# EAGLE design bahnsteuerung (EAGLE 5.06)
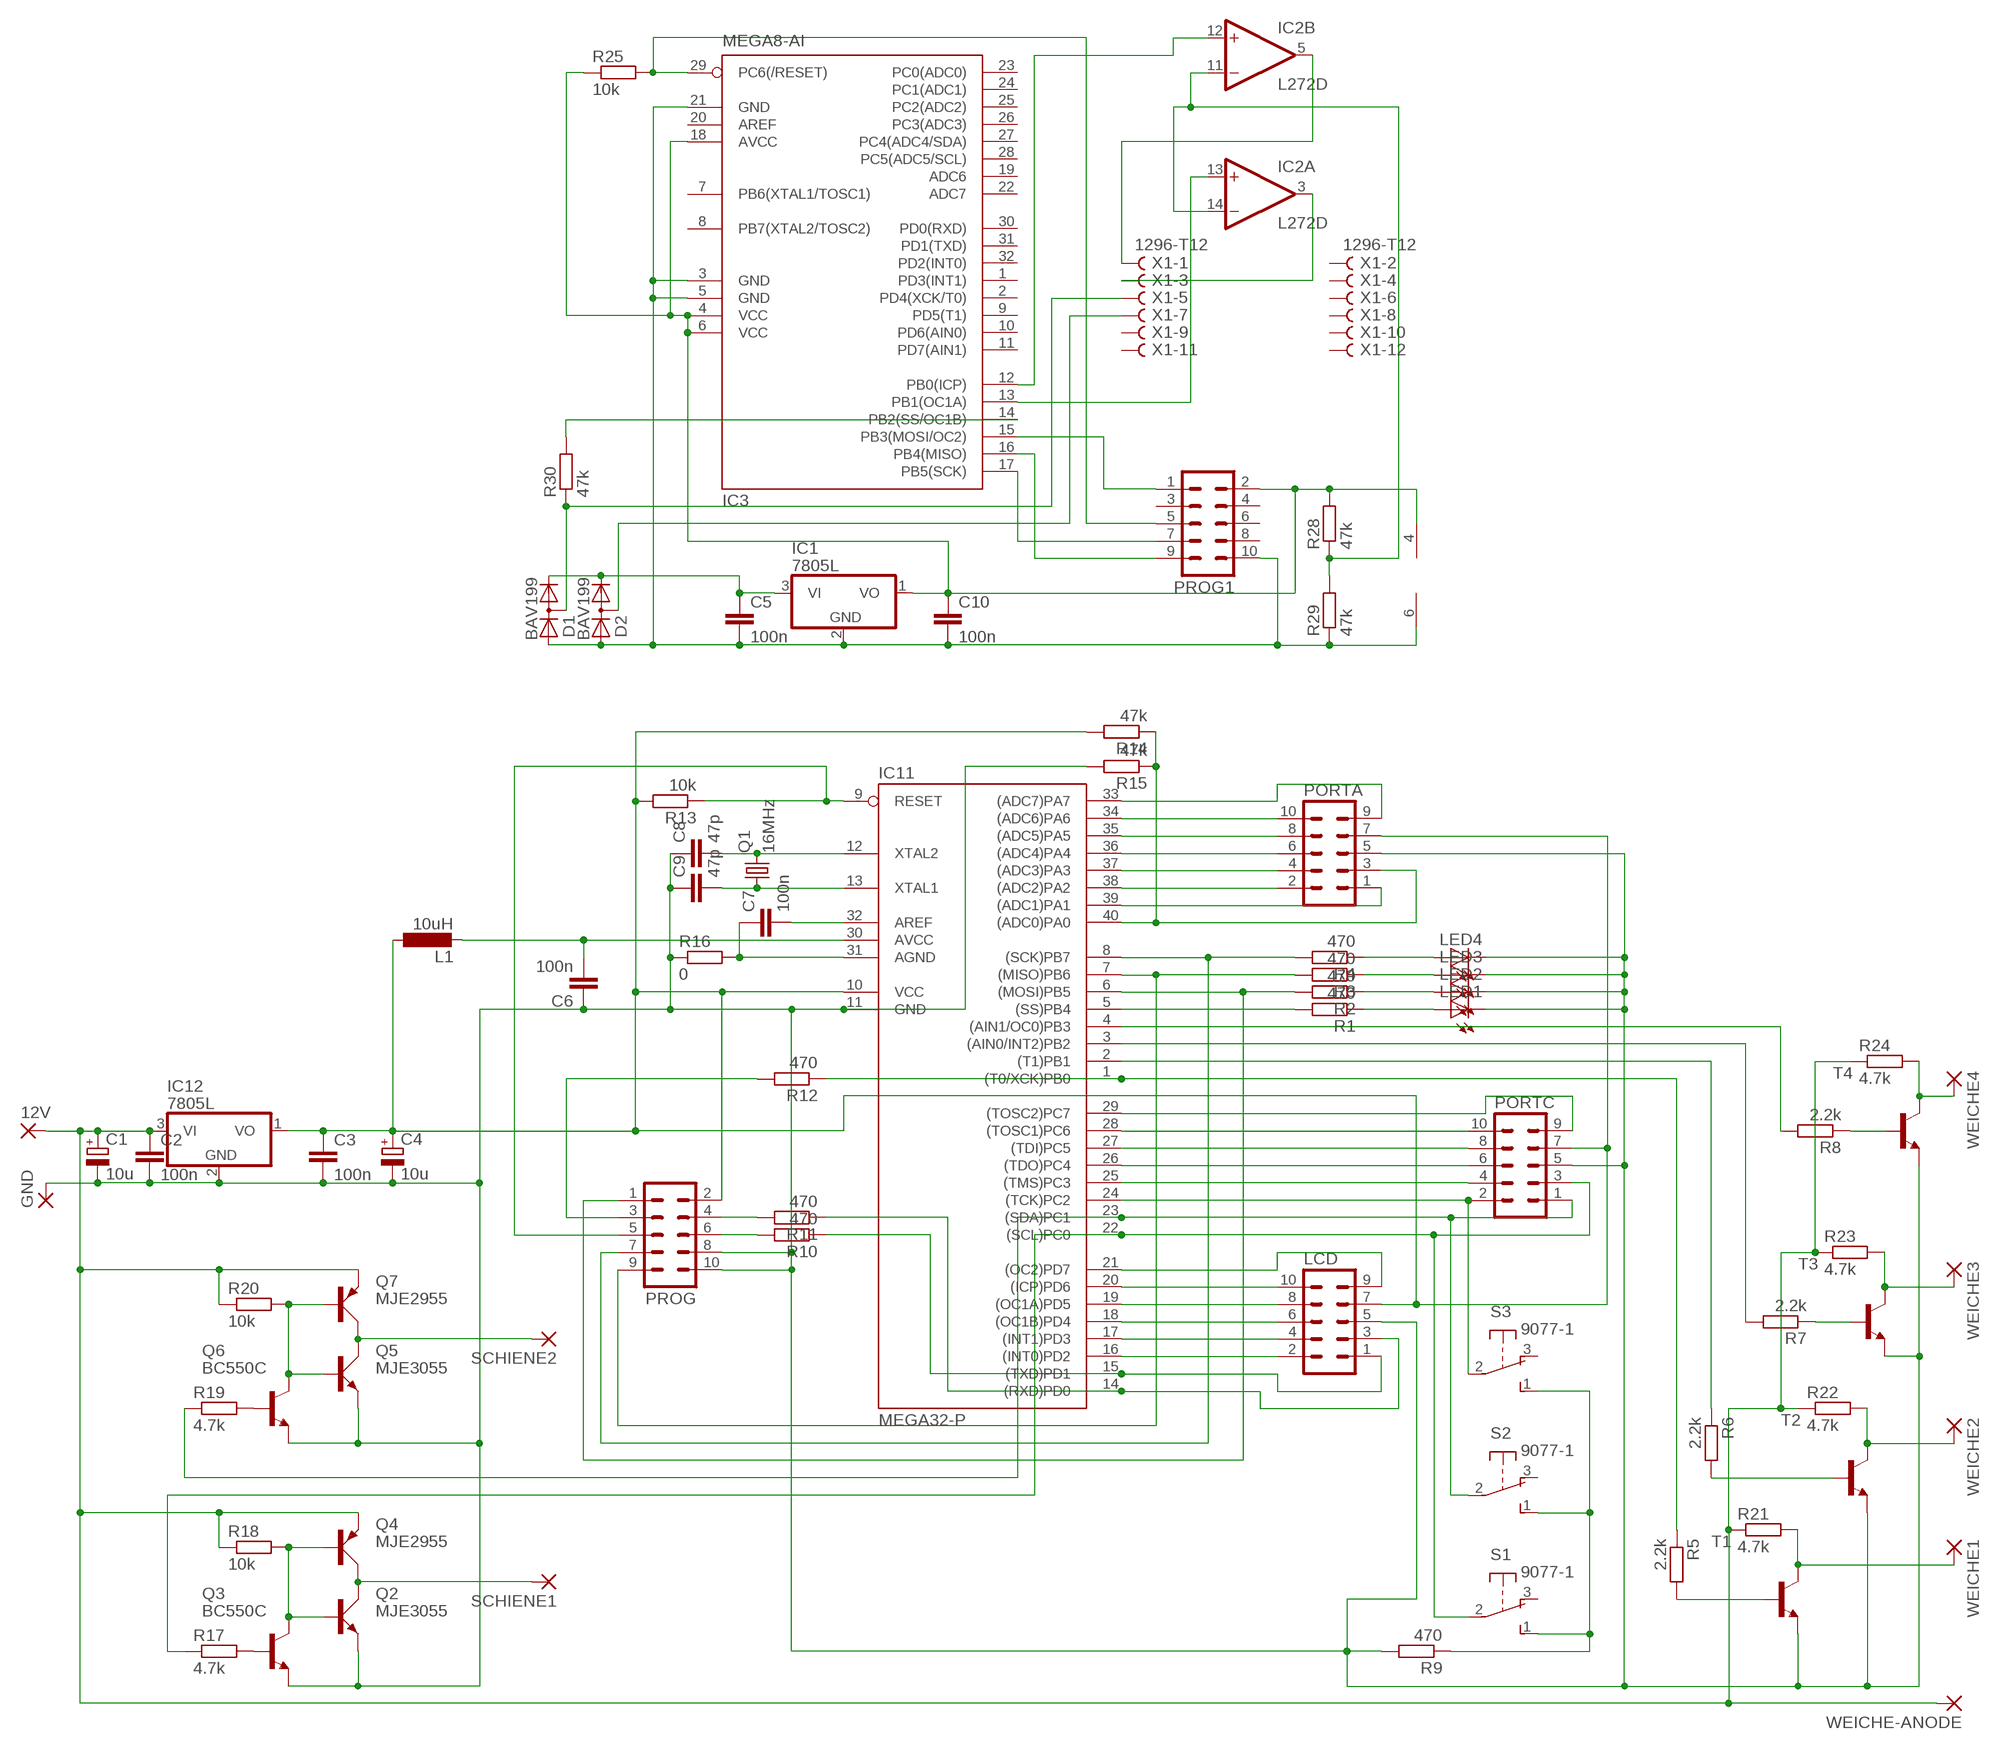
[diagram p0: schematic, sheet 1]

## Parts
12V  1,6/0,8  [1,6/0,8]
C1  10u  CPOL-EUE2.5-5  [E2,5-5]
C2  100n  C5/2.5  [C5B2.5]
C3  100n  C5/2.5  [C5B2.5]
C4  10u  CPOL-EUE2.5-5  [E2,5-5]
C5  100n  C-EUC0402  [C0402]
C6  100n  C5/2.5  [C5B2.5]
C7  100n  C2.5/2  [C2.5-2]
C8  47p  C2.5/2  [C2.5-2]
C9  47p  C2.5/2  [C2.5-2]
C10  100n  C-EUC0402  [C0402]
D1  BAV199  [SOT23]
D2  BAV199  [SOT23]
GND  1,6/0,8  [1,6/0,8]
IC1  7805L  [TO92]
IC2  L272D  [SO16]
IC3  MEGA8-AI  [TQFP32-08]
IC11  MEGA32-P  [DIL40]
IC12  7805L  [TO92]
L1  10uH  L-EU0204/7  [0204/7@1]
LCD  ML10  [ML10]
LED1  LED3MM  [LED3MM]
LED2  LED3MM  [LED3MM]
LED3  LED3MM  [LED3MM]
LED4  LED3MM  [LED3MM]
PORTA  ML10  [ML10]
PORTC  ML10  [ML10]
PROG  ML10  [ML10]
PROG1  ML10  [ML10]
Q1  16MHz  CRYTALHC49U-V  [HC49U-V]
Q2  MJE3055  [TO220AV]
Q3  BC550C  [TO92-EBC]
Q4  MJE2955  [TO220AV@1]
Q5  MJE3055  [TO220AV]
Q6  BC550C  [TO92-EBC]
Q7  MJE2955  [TO220AV@1]
R1  470  R-EU_0204/7  [0204/7]
R2  470  R-EU_0204/7  [0204/7]
R3  470  R-EU_0204/7  [0204/7]
R4  470  R-EU_0204/7  [0204/7]
R5  2.2k  R-EU_0204/7  [0204/7]
R6  2.2k  R-EU_0204/7  [0204/7]
R7  2.2k  R-EU_0204/7  [0204/7]
R8  2.2k  R-EU_0204/7  [0204/7]
R9  470  R-EU_0204/7  [0204/7]
R10  470  R-EU_0204/7  [0204/7]
R11  470  R-EU_0204/7  [0204/7]
R12  470  R-EU_0204/7  [0204/7]
R13  10k  R-EU_0204/7  [0204/7]
R14  47k  R-EU_0204/7  [0204/7]
R15  47k  R-EU_0204/7  [0204/7]
R16  0  R-EU_0204/2V  [0204V]
R17  4.7k  R-EU_0204/2V  [0204V]
R18  10k  R-EU_0204/7  [0204/7]
R19  4.7k  R-EU_0204/2V  [0204V]
R20  10k  R-EU_0204/7  [0204/7]
R21  4.7k  R-EU_0204/2V  [0204V]
R22  4.7k  R-EU_0204/2V  [0204V]
R23  4.7k  R-EU_0204/2V  [0204V]
R24  4.7k  R-EU_0204/2V  [0204V]
R25  10k  R-EU_MELF0102R  [MINI_MELF-0102R]
R28  47k  R-EU_MELF0102R  [MINI_MELF-0102R]
R29  47k  R-EU_MELF0102R  [MINI_MELF-0102R]
R30  47k  R-EU_MELF0102R  [MINI_MELF-0102R]
S1  9077-1  [9077-1]
S2  9077-1  [9077-1]
S3  9077-1  [9077-1]
SCHIENE1  1,6/0,8  [1,6/0,8]
SCHIENE2  1,6/0,8  [1,6/0,8]
T1  -NPN-TO220V  [TO220V]
T2  -NPN-TO220V  [TO220V]
T3  -NPN-TO220V  [TO220V]
T4  -NPN-TO220V  [TO220V]
WEICHE1  1,6/0,8  [1,6/0,8]
WEICHE2  1,6/0,8  [1,6/0,8]
WEICHE3  1,6/0,8  [1,6/0,8]
WEICHE4  1,6/0,8  [1,6/0,8]
WEICHE-ANODE  1,6/0,8  [1,6/0,8]
X1  1296-T12  [1296-12]

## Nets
AGND [mitteldick]: C7.1 IC11.31(AGND) R16.2
AREF [mitteldick]: C7.2 IC11.32(AREF)
AVCC [mitteldick]: C6.2 IC11.30(AVCC) L1.2
GND [mitteldick]: C1.- C2.2 C3.2 C4.- C6.1 C8.1 C9.1 GND.1(P) IC11.11(GND) IC12.2(GND) LCD.5 LED1.K(C) LED2.K(C) LED3.K(C) LED4.K(C) PORTA.5 PORTC.5 PROG.8 PROG.10 Q2.E Q3.E Q5.E Q6.E R9.2 R15.2 R16.1 T1.3(E) T2.3(E) T3.3(E) T4.3(E)
GND1: C5.2 C10.2 D1.1(A) D2.1(A) IC1.2(GND) IC2.6(P:GND) IC3.3(GND) IC3.5(GND) IC3.21(GND) PROG1.10 R29.1
N$1: IC11.22((SCL)PC0) PORTC.3 R17.1 S1.2(P)
N$2: IC11.23((SDA)PC1) PORTC.1 R19.1 S2.2(P)
N$3: R8.1 T4.1(B)
N$4: IC11.4((AIN1/OC0)PB3) R8.2
N$5: R24.2 T4.2(C) WEICHE4.1(P)
N$6: IC11.5((SS)PB4) R1.2
N$7: LED1.A R1.1
N$8: LED2.A R2.1
N$9: LED3.A R3.1
N$10: LED4.A R4.1
N$11 [mitteldick]: IC11.16((INT0)PD2) LCD.2
N$12 [mitteldick]: IC11.17((INT1)PD3) LCD.4
N$13 [mitteldick]: IC11.18((OC1B)PD4) LCD.6
N$14 [mitteldick]: IC11.19((OC1A)PD5) LCD.8
N$15 [mitteldick]: IC11.20((ICP)PD6) LCD.10
N$16 [mitteldick]: IC11.21((OC2)PD7) LCD.9
N$17 [mitteldick]: IC11.25((TMS)PC3) PORTC.4
N$18 [mitteldick]: IC11.26((TDO)PC4) PORTC.6
N$19 [mitteldick]: IC11.27((TDI)PC5) PORTC.8
N$20 [mitteldick]: IC11.28((TOSC1)PC6) PORTC.10
N$21 [mitteldick]: IC11.29((TOSC2)PC7) PORTC.9
N$22 [mitteldick]: IC11.39((ADC1)PA1) PORTA.1
N$23 [mitteldick]: IC11.38((ADC2)PA2) PORTA.2
N$24 [mitteldick]: IC11.37((ADC3)PA3) PORTA.4
N$25 [mitteldick]: IC11.36((ADC4)PA4) PORTA.6
N$26 [mitteldick]: IC11.35((ADC5)PA5) PORTA.8
N$27 [mitteldick]: IC11.34((ADC6)PA6) PORTA.10
N$28 [mitteldick]: IC11.33((ADC7)PA7) PORTA.9
N$29 [mitteldick]: R9.1 S1.1(S) S2.1(S) S3.1(S)
N$30: Q6.B R19.2
N$31: Q3.B R17.2
N$32: Q2.C Q4.C SCHIENE1.1(P)
N$34: Q2.B Q3.C Q4.B R18.2
N$35: Q5.C Q7.C SCHIENE2.1(P)
N$37: Q5.B Q6.C Q7.B R20.2
N$38: IC2.3(A:OUT) X1.3
N$40: IC3.29(PC6(/RESET)) PROG1.5 R25.2
N$41: IC3.16(PB4(MISO)) PROG1.9
N$42: IC3.17(PB5(SCK)) PROG1.7
N$43: IC3.15(PB3(MOSI/OC2)) PROG1.1
N$44: D1.3(AC) R30.1 X1.5
N$45: C5.1 D1.2(C) D2.2(C) IC1.3(VI)
N$46: D2.3(AC) X1.7
N$52: IC2.5(B:OUT) X1.1
N$53: IC2.13(A:+IN) IC3.13(PB1(OC1A))
N$54: IC2.12(B:+IN) IC3.12(PB0(ICP))
N$55: IC2.11(B:-IN) IC2.14(A:-IN) R28.1 R29.2
N$56: IC3.14(PB2(SS/OC1B)) R30.2
N$122: IC11.40((ADC0)PA0) PORTA.3 R14.1 R15.1
N$135: IC11.6((MOSI)PB5) PROG.1 R2.2
N$136: IC11.7((MISO)PB6) PROG.9 R3.2
N$147: IC11.14((RXD)PD0) LCD.3 R11.1
N$149: R7.1 T3.1(B)
N$150: IC11.1((T0/XCK)PB0) R5.1 R12.1
N$152: C8.2 IC11.12(XTAL2) Q1.2
N$153: C9.2 IC11.13(XTAL1) Q1.1
N$156: IC11.9(RESET) PROG.5 R13.1
N$157: PROG.4 R11.2
N$158: PROG.6 R10.2
N$159: PROG.3 R12.2
N$160: IC11.24((TCK)PC2) PORTC.2 S3.2(P)
N$161: IC11.15((TXD)PD1) LCD.1 R10.1
N$164: IC11.3((AIN0/INT2)PB2) R7.2
N$166: IC11.2((T1)PB1) R6.1
N$167: R5.2 T1.1(B)
N$168: R6.2 T2.1(B)
N$170: IC11.8((SCK)PB7) PROG.7 R4.2
N$172 [mitteldick]: R21.2 T1.2(C) WEICHE1.1(P)
N$173 [mitteldick]: R22.2 T2.2(C) WEICHE2.1(P)
N$174 [mitteldick]: R23.2 T3.2(C) WEICHE3.1(P)
VCC [mitteldick]: C3.1 C4.+ IC11.10(VCC) IC12.1(VO) L1.1 LCD.7 PORTA.7 PORTC.7 PROG.2 R13.2 R14.2
VCC1 [mitteldick]: 12V.1(P) C1.+ C2.1 IC12.3(VI) Q4.E Q7.E R18.1 R20.1 R21.1 R22.1 R23.1 R24.1 WEICHE-ANODE.1(P)
VCC2: C10.1 IC1.1(VO) IC2.4(P:V+) IC3.4(VCC) IC3.6(VCC) IC3.18(AVCC) PROG1.2 R25.1 R28.2
Unconnected: IC3.1(PD3(INT1)) IC3.2(PD4(XCK/T0)) IC3.7(PB6(XTAL1/TOSC1)) IC3.8(PB7(XTAL2/TOSC2)) IC3.9(PD5(T1)) IC3.10(PD6(AIN0)) IC3.11(PD7(AIN1)) IC3.19(ADC6) IC3.20(AREF) IC3.22(ADC7) IC3.23(PC0(ADC0)) IC3.24(PC1(ADC1)) IC3.25(PC2(ADC2)) IC3.26(PC3(ADC3)) IC3.27(PC4(ADC4/SDA)) IC3.28(PC5(ADC5/SCL)) IC3.30(PD0(RXD)) IC3.31(PD1(TXD)) IC3.32(PD2(INT0)) PROG1.3 PROG1.4 PROG1.6 PROG1.8 S1.3(O) S2.3(O) S3.3(O) X1.2 X1.4 X1.6 X1.8 X1.9 X1.10 X1.11 X1.12

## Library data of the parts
12V GND SCHIENE1 SCHIENE2 WEICHE1-WEICHE4 WEICHE-ANODE = wirepad:1,6/0,8: THROUGH-HOLE PAD
C1 C4 = rcl:CPOL-EU: POLARIZED CAPACITOR, European symbol
C2 C3 C6-C9 = capacitor-wima:C: CAPACITOR
C5 C10 = rcl:C-EU: CAPACITOR, European symbol
D1 D2 = diode:BAV199: DIODE low-leakage double diode
IC1 IC12 = linear:78*: Positive VOLTAGE REGULATOR Source: http://cache.national.com/ds/LM/LM78L05.pdf http://www.fairchildsemi.com/ds/LM/LM7805.pdf
IC2 = linear:L272: OP AMP
IC3 = atmel:MEGA8: MICROCONTROLLER 8 Kbytes FLASH, 1 kbytes SRAM, 512 bytes EEPROM, USART, 6-channel 10 bit ADC, 2-channel 8 bit ADC Pin compatible with Atmega48, ATMega88, ATMega168 Source: avr.lbr
IC11 = atmel:MEGA32-P: MICROCONTROLLER 32 Kbytes FLASH 2 Kbytes SRAM 1 Kbytes EEPROM USART 8-channel 10 bit ADC Source: www.atmel.com .. doc2503.pdf
L1 = rcl:L-EU: INDUCTOR, European symbol
LCD PORTA PORTC PROG PROG1 = con-harting-ml:ML10: HARTING
LED1-LED4 = led:LED: LED
Q1 = crystal:CRYTAL: CRYSTAL
Q2 Q5 = transistor-power:MJE3055: NPN TRANSISTOR
Q3 Q6 = transistor-npn:BC550*: NPN Transistor
Q4 Q7 = transistor-power:MJE2955: PNP TRANSISTOR
R1-R25 R28-R30 = rcl:R-EU_: RESISTOR, European symbol
S1-S3 = switch-misc:9077-1: MARQUARDT SWITCH
T1-T4 = transistor:*-NPN-: NPN Transistror
X1 = con-leotronics:1296-T12: 1.27mm SINGLE ROW FEMALE SOCKET Source: http://www.leotronics.co.uk/Conexcon/Data%20Sheets/sec.%20A/1296ing.pdf

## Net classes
1 dick: width 1.016 mm, clearance 0.61 mm
2 mitteldick: width 0.762 mm

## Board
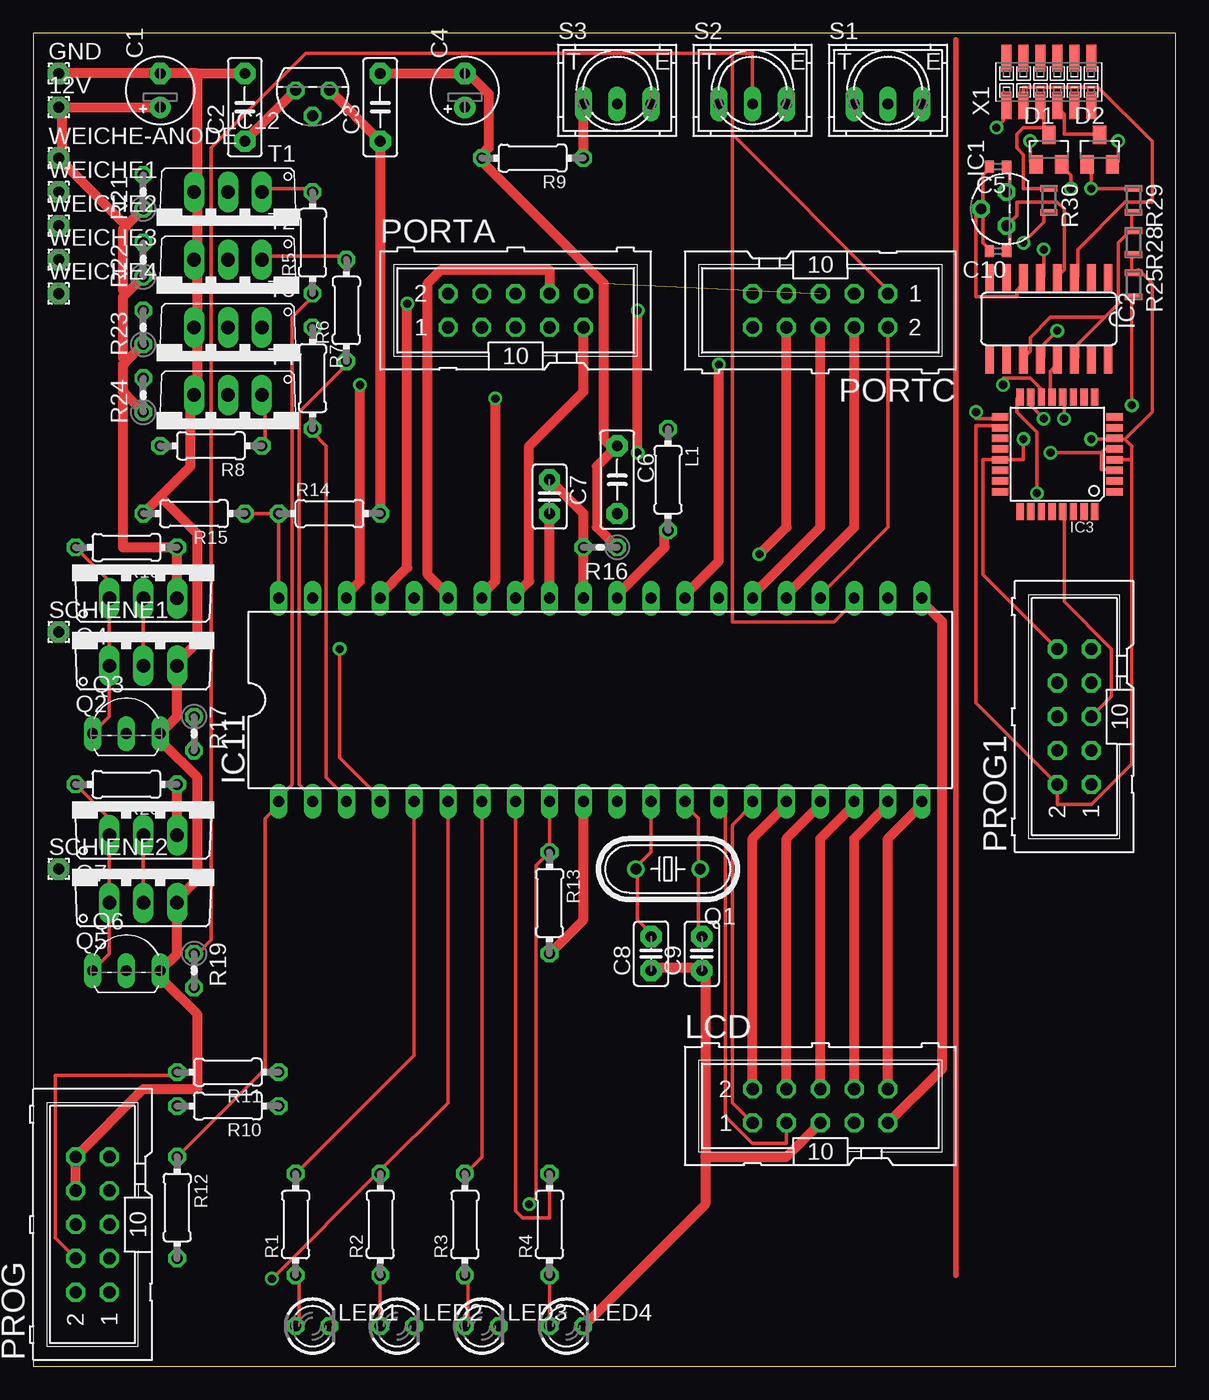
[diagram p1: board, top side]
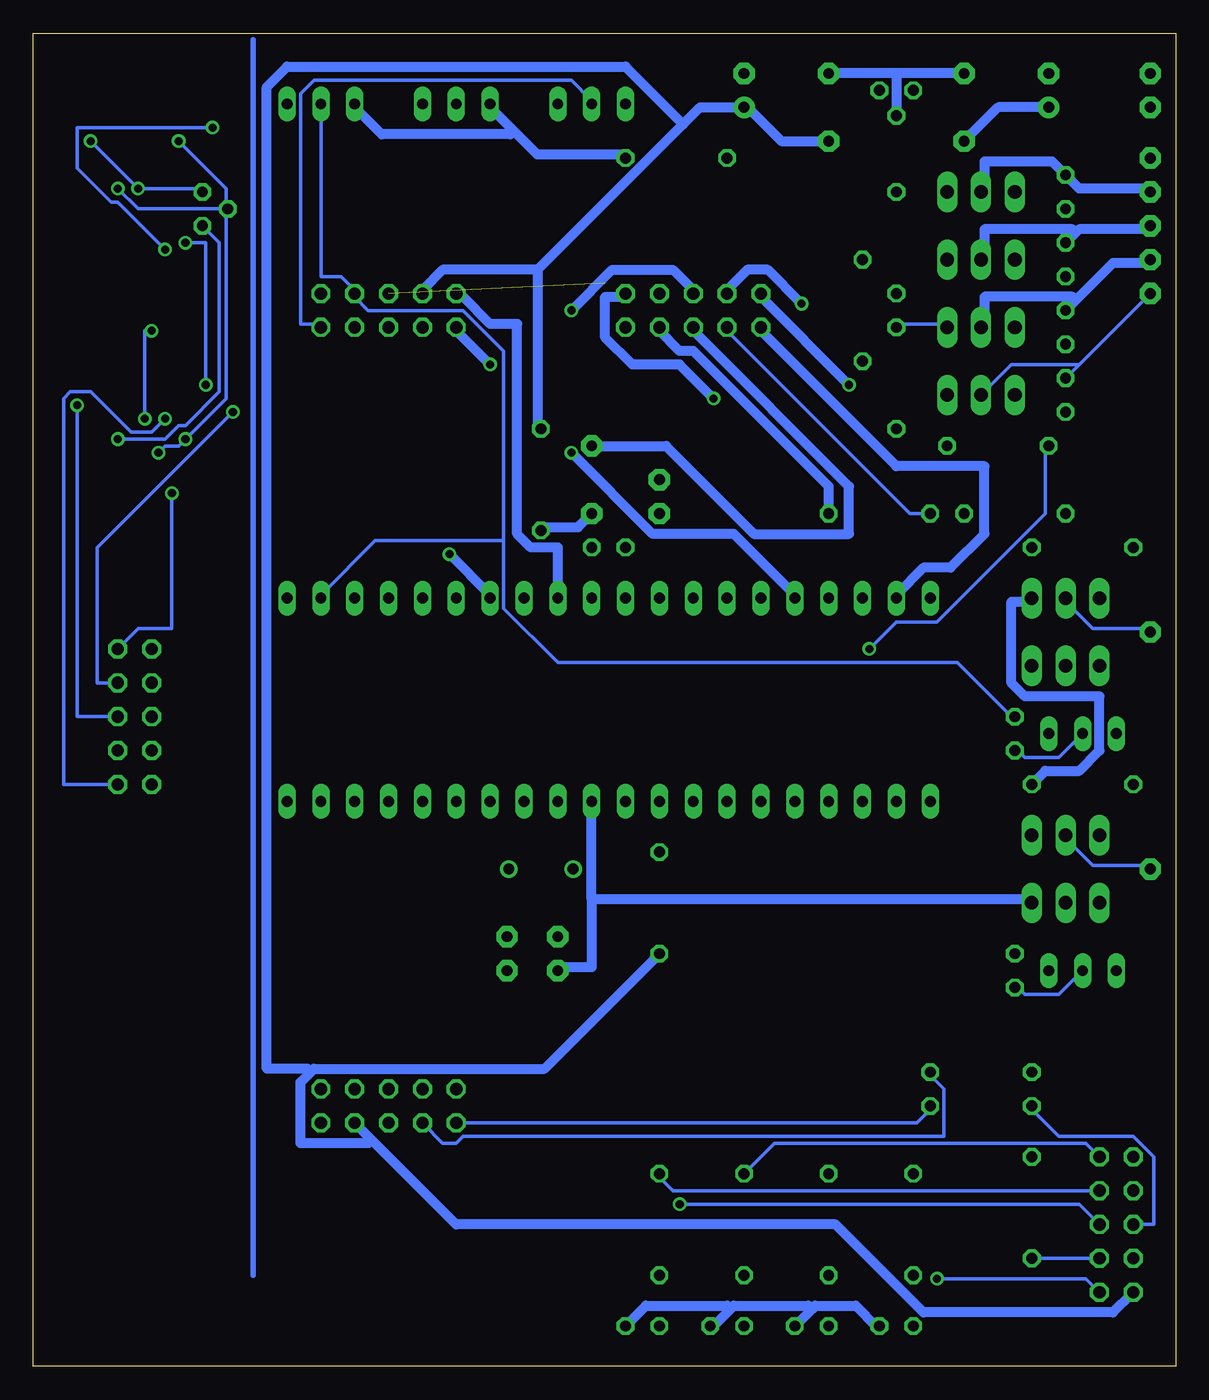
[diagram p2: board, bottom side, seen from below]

Size 85.7 x 100 mm. Coordinates in mm from the lower left corner, seen from the top.
Outline: 0,0 85.7,0 85.7,100 0,100 0,0
Copper layers (1*16): Top 0.035mm / dielectric 1.5mm / Bottom 0.035mm
Design rules "default": minimum track width 10mil, minimum drill 24mil, track to track 8mil, track to pad 8mil, pad to pad 8mil, via to via 8mil, smd to smd 8mil, copper to edge 40mil, drill to drill 8mil, minimum pad ring 10mil, minimum via ring 8mil, stop-mask expansion 4mil, vias tented up to drill 0mil, thermal gap 10mil

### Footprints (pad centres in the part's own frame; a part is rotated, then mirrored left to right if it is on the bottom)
1,6/0,8 = drill 0.813 pad 1.6 octagon: 1 0,0
E2,5-5 = drill 0.813 pad 1.6 round: + -1.27,0 | drill 0.813 pad 1.6 octagon: - 1.27,0
C5B2.5 = drill 0.813 pad 1.6 octagon: 1 -2.54,0; 2 2.54,0
C0402 = smd 0.7 x 0.9: 1 -0.65,0; 2 0.65,0
C2.5-2 = drill 0.813 pad 1.6 octagon: 1 -1.27,0; 2 1.27,0
SOT23 = smd 1 x 1.4: 1 -0.95,-1.1; 2 0.95,-1.1; 3 0,1.1
TO92 = drill 0.813 octagon: 1 -1.27,0; 2 0,1.905; 3 1.27,0
SO16 = smd 0.66 x 2.032: 1 -4.445,-3.073; 2 -3.175,-3.073; 3 -1.905,-3.073; 4 -0.635,-3.073; 5 0.635,-3.073; 6 1.905,-3.073; 7 3.175,-3.073; 8 4.445,-3.073; 9 4.445,3.073; 10 3.175,3.073; 11 1.905,3.073; 12 0.635,3.073; 13 -0.635,3.073; 14 -1.905,3.073; 15 -3.175,3.073; 16 -4.445,3.073
TQFP32-08 = smd 1.27 x 0.559: 1 -4.293,2.8; 2 -4.293,2; 3 -4.293,1.2; 4 -4.293,0.4; 5 -4.293,-0.4; 6 -4.293,-1.2; 7 -4.293,-2; 8 -4.293,-2.8; 17 4.293,-2.8; 18 4.293,-2; 19 4.293,-1.2; 20 4.293,-0.4; 21 4.293,0.4; 22 4.293,1.2; 23 4.293,2; 24 4.293,2.8 | smd 0.559 x 1.27: 9 -2.8,-4.293; 10 -2,-4.293; 11 -1.2,-4.293; 12 -0.4,-4.293; 13 0.4,-4.293; 14 1.2,-4.293; 15 2,-4.293; 16 2.8,-4.293; 25 2.8,4.293; 26 2,4.293; 27 1.2,4.293; 28 0.4,4.293; 29 -0.4,4.293; 30 -1.2,4.293; 31 -2,4.293; 32 -2.8,4.293
DIL40 = drill 0.813 long: 1 -24.13,-7.62; 2 -21.59,-7.62; 3 -19.05,-7.62; 4 -16.51,-7.62; 5 -13.97,-7.62; 6 -11.43,-7.62; 7 -8.89,-7.62; 8 -6.35,-7.62; 9 -3.81,-7.62; 10 -1.27,-7.62; 11 1.27,-7.62; 12 3.81,-7.62; 13 6.35,-7.62; 14 8.89,-7.62; 15 11.43,-7.62; 16 13.97,-7.62; 17 16.51,-7.62; 18 19.05,-7.62; 19 21.59,-7.62; 20 24.13,-7.62; 21 24.13,7.62; 22 21.59,7.62; 23 19.05,7.62; 24 16.51,7.62; 25 13.97,7.62; 26 11.43,7.62; 27 8.89,7.62; 28 6.35,7.62; 29 3.81,7.62; 30 1.27,7.62; 31 -1.27,7.62; 32 -3.81,7.62; 33 -6.35,7.62; 34 -8.89,7.62; 35 -11.43,7.62; 36 -13.97,7.62; 37 -16.51,7.62; 38 -19.05,7.62; 39 -21.59,7.62; 40 -24.13,7.62
0204/7@1 = drill 0.813 octagon: 1 -3.81,0; 2 3.81,0
ML10 = drill 0.914 octagon: 1 -5.08,-1.27; 2 -5.08,1.27; 3 -2.54,-1.27; 4 -2.54,1.27; 5 0,-1.27; 6 0,1.27; 7 2.54,-1.27; 8 2.54,1.27; 9 5.08,-1.27; 10 5.08,1.27
LED3MM = drill 0.813 octagon: A -1.27,0; K 1.27,0
HC49U-V = drill 0.813 round: 1 -2.413,0; 2 2.413,0
TO220AV = drill 1.016 long: B -2.54,-2.54; C 0,-2.54; E 2.54,-2.54
TO92-EBC = drill 0.813 long: B 0,-1.27; C -2.54,-1.27; E 2.54,-1.27
TO220AV@1 = drill 1.016 long: B -2.54,-2.54; C 0,-2.54; E 2.54,-2.54
0204/7 = drill 0.813 octagon: 1 -3.81,0; 2 3.81,0
0204V = drill 0.813 octagon: 1 -1.27,0; 2 1.27,0
MINI_MELF-0102R = smd 0.5 x 1.3: 1 -0.9,0; 2 0.9,0
9077-1 = drill 0.813 long: 1 -2.54,-1.016; 2 0,-1.016; 3 2.54,-1.016
TO220V = drill 1.016 long: 1 -2.54,-2.54; 2 0,-2.54; 3 2.54,-2.54
1296-12 = smd 0.76 x 2.05: 1 -3.175,-1.78; 2 -3.175,1.78; 3 -1.905,-1.78; 4 -1.905,1.78; 5 -0.635,-1.78; 6 -0.635,1.78; 7 0.635,-1.78; 8 0.635,1.78; 9 1.905,-1.78; 10 1.905,1.78; 11 3.175,-1.78; 12 3.175,1.78

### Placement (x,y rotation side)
12V  1.9,94.45 0 top
C1  9.52,95.72 90 top
C2  15.87,94.45 90 top
C3  26.03,94.45 90 top
C4  32.38,95.72 90 top
C5  72.38,90 180 top
C6  43.81,66.51 270 top
C7  38.73,65.24 270 top
C8  46.35,30.95 90 top
C9  50.16,30.95 90 top
C10  72.38,83.66 180 top
D1  76.19,91.28 0 top
D2  80,91.28 0 top
GND  1.9,96.99 0 top
IC1  73.02,86.83 90 top
IC2  76.19,78.58 180 top
IC3  76.83,68.41 180 top
IC11  42.54,50 0 top
IC12  20.95,95.72 180 top
L1  47.62,66.51 270 top
LCD  59.05,19.52 0 top
LED1  20.95,3.01 0 top
LED2  27.3,3.01 0 top
LED3  33.65,3.01 0 top
LED4  40,3.01 0 top
PORTA  36.19,79.21 0 top
PORTC  59.05,79.21 180 top
PROG  4.44,10.63 90 top
PROG1  78.1,48.73 90 top
Q1  47.62,37.3 180 top
Q2  8.25,55.08 0 top
Q3  6.98,48.73 0 top
Q4  8.25,60.16 0 top
Q5  8.25,37.3 0 top
Q6  6.98,30.95 0 top
Q7  8.25,42.38 0 top
R1  19.68,10.63 90 top
R2  26.03,10.63 90 top
R3  32.38,10.63 90 top
R4  38.73,10.63 90 top
R5  20.95,84.29 90 top
R6  23.49,79.21 90 top
R7  20.95,74.13 270 top
R8  13.33,69.05 180 top
R9  37.46,90.64 180 top
R10  14.6,19.52 180 top
R11  14.6,22.06 180 top
R12  10.79,11.9 270 top
R13  38.73,34.76 270 top
R14  22.22,63.97 0 top
R15  12.06,63.97 180 top
R16  42.54,61.43 180 top
R17  12.06,47.46 270 top
R18  6.98,61.43 180 top
R19  12.06,29.68 270 top
R20  6.98,43.65 180 top
R21  8.25,88.1 90 top
R22  8.25,83.02 90 top
R23  8.25,77.94 90 top
R24  8.25,72.86 90 top
R25  82.55,81.11 270 top
R28  82.55,84.29 270 top
R29  82.55,87.47 270 top
R30  76.19,87.47 270 top
S1  64.13,95.72 0 top
S2  53.97,95.72 0 top
S3  43.81,95.72 0 top
SCHIENE1  1.9,55.08 0 top
SCHIENE2  1.9,37.3 0 top
T1  14.6,85.56 180 top
T2  14.6,80.48 180 top
T3  14.6,75.4 180 top
T4  14.6,70.32 180 top
WEICHE1  1.9,88.1 0 top
WEICHE2  1.9,85.56 0 top
WEICHE3  1.9,83.02 0 top
WEICHE4  1.9,80.48 0 top
WEICHE-ANODE  1.9,90.64 0 top
X1  76.19,96.36 0 top

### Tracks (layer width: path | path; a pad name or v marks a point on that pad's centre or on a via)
AGND
  Top 0.762: IC11.31 R16.2 41.27,63.97 C7.1
AREF
  Top 0.762: IC11.32 C7.2
AVCC
  Top 0.762: IC11.30 43.81,57.87 47.37,61.43 47.37,62.45 L1.2
  Bottom 0.762: C6.2 44.83,62.95 47.37,62.95 L1.2
GND  (1 unrouted)
  Top 0.762: R16.1 42.29,62.95 42.29,67.53 C6.1 43.3,69.05 42.79,69.56 42.79,81.24 33.65,90.39 R9.2 33.65,90.89 34.16,91.4 34.16,95.47 32.63,96.99 C4.- C3.2 | GND.1 C1.- 12.31,96.99 | 12.31,96.99 C2.2 | LCD.5 56.51,15.71 50.41,15.71 | 50.41,15.71 50.41,29.43 C9.1 49.91,29.93 46.35,29.93 C8.1 | LED4.K 50.41,12.15 50.41,15.71 | PROG.8 PROG.10 8.25,20.79 12.31,20.79 12.31,26.38 9.77,28.92 9.77,29.43 Q6.E 10.79,30.95 Q5.E 10.79,35.01 12.31,36.54 12.31,44.16 9.77,46.7 9.77,47.21 Q3.E 10.79,48.73 Q2.E 10.79,52.79 12.31,54.32 12.31,62.45 9.52,65.24 | 9.52,65.24 11.81,67.53 11.81,72.61 T4.3 12.31,73.11 12.31,77.69 T3.3 12.31,78.19 12.31,82.77 T2.3 12.31,83.27 12.31,87.85 T1.3 12.31,88.35 12.31,96.99 | 9.52,65.24 R15.2
  Bottom 0.762: C6.1 38.22,69.05 31.62,62.45 24.51,62.45 24.51,66 36.19,77.69 PORTA.5 | C2.2 20.95,96.99 | 20.95,96.99 IC12.2 | 20.95,96.99 C3.2 | 27.3,4.28 LED2.K | 27.3,4.28 27.05,4.53 24,4.53 22.47,3.01 LED1.K | 33.4,4.28 33.14,4.53 27.55,4.53 27.3,4.28 | 33.4,4.28 34.67,3.01 LED3.K | LED4.K 39.75,4.53 33.65,4.53 33.4,4.28 | 43.81,35.01 43.81,29.93 46.35,29.93 C8.1 | 43.81,35.01 IC11.11 | 43.81,35.01 10.79,35.01 Q5.E
GND1  (via drill 0.61)
  Top 0.254: PROG1.10 71.24,59.4 71.24,68.03 72.26,68.03 IC3.21 72.77,68.03 74.29,68.03 v74.29,69.56 | R29.1 82.42,88.35 v79.37,88.35 79.37,89.88 D2.1 | 71.24,86.83 71.24,84.29 71.75,83.78 C10.2 | 71.24,86.83 71.24,89.37 71.75,89.88 C5.2 | 71.24,86.83 IC1.2 70.73,86.83 70.73,80.23 73.78,80.23 73.78,80.73 74.29,81.24 IC2.6 | v74.8,91.91 74.8,90.39 D1.1 | 80.13,68.54 80.13,67.27 80.89,67.27 IC3.3 | 80.13,68.54 80.39,68.8 80.89,68.8 IC3.5 | v76.32,68.54 80.13,68.54
  Bottom 0.254: v74.8,91.91 71.24,88.35 71.24,86.83 | v79.37,88.35 77.85,86.83 71.24,86.83 | 71.24,86.83 71.24,72.61 v74.29,69.56 74.8,69.05 75.81,69.05 v76.32,68.54 | 71.24,86.83 IC1.2
N$1
  Bottom 0.254: S1.2 64.13,81.75 62.61,81.75 61.59,80.73 PORTC.3 61.59,80.23 60.57,79.21 53.46,79.21 50.41,76.16 50.41,61.94 | 50.41,61.94 50.41,56.86 46.35,52.79 16.38,52.79 12.31,48.73 R17.1 | 50.41,61.94 60.07,61.94 64.13,57.87 IC11.22
N$2
  Top 0.254: 52.45,98.51 53.97,98.51 S2.2 | 52.45,98.51 20.44,98.51 13.33,91.4 13.33,31.97 12.31,30.95 R19.1 | 52.45,98.51 52.45,92.42 | 52.45,92.42 52.45,55.84 60.07,55.84 61.59,57.37 IC11.23 | 52.45,92.42 64.13,80.73 PORTC.1
N$3
  Top 0.254: R8.1 17.39,69.05 17.39,72.61 T4.1
N$4  (via drill 0.61)
  Top 0.254: v22.98,53.81 22.98,45.68 26.03,42.63 IC11.4
  Bottom 0.254: v22.98,53.81 20.95,55.84 17.9,55.84 9.77,63.97 9.77,69.05 R8.2
N$5
  Bottom 0.254: 7.23,75.15 R24.2 | WEICHE4.1 7.23,75.15 | 7.23,75.15 12.31,75.15 T4.2
N$6
  Top 0.254: R1.2 28.57,23.33 IC11.5
N$7
  Top 0.254: LED1.A 19.93,3.01 19.93,6.57 R1.1
N$8
  Top 0.254: LED2.A R2.1
N$9
  Top 0.254: LED3.A 32.63,3.01 32.63,6.57 R3.1
N$10
  Top 0.254: LED4.A R4.1
N$11
  Top 0.762: LCD.2 53.97,39.59 56.51,42.13 IC11.16
N$12
  Top 0.762: LCD.4 56.51,39.59 59.05,42.13 IC11.17
N$13
  Top 0.762: LCD.6 59.05,39.59 61.59,42.13 IC11.18
N$14
  Top 0.762: LCD.8 61.59,39.59 64.13,42.13 IC11.19
N$15
  Top 0.762: LCD.10 64.13,39.59 66.67,42.13 IC11.20
N$16
  Top 0.762: LCD.9 68.19,22.31 68.19,55.84 66.67,57.37 IC11.21
N$17
  Top 0.762: IC11.25 56.51,57.87 61.59,62.95 PORTC.4
N$18
  Top 0.762: IC11.26 53.97,57.87 59.05,62.95 PORTC.6
N$19  (via drill 0.61)
  Top 0.762: v54.48,60.92 56.51,62.95 PORTC.8
  Bottom 0.762: v54.48,60.92 51.43,57.87 IC11.27
N$20  (via drill 0.61)
  Top 0.762: v51.43,75.15 51.43,60.41 48.89,57.87 IC11.28
  Bottom 0.762: v51.43,75.15 53.97,77.69 PORTC.10
N$21
  Bottom 0.762: IC11.29 46.35,61.43 48.38,61.43 49.4,62.45 49.4,78.19 51.43,78.19 53.46,80.23 53.97,80.23 PORTC.9
N$22
  Bottom 0.762: IC11.39 20.95,57.87 18.92,59.91 16.89,59.91 14.35,62.45 14.35,67.53 20.95,67.53 31.11,77.69 PORTA.1
N$23  (via drill 0.61)
  Top 0.762: v24.51,73.62 24.51,58.89 23.49,57.87 IC11.38
  Bottom 0.762: v24.51,73.62 31.11,80.23 PORTA.2
N$24  (via drill 0.61)
  Top 0.762: v28.06,79.72 28.06,59.91 26.03,57.87 IC11.37
  Bottom 0.762: v28.06,79.72 30.6,82.26 32.13,82.26 33.65,80.73 PORTA.4
N$25  (via drill 0.61)
  Top 0.762: v45.33,68.54 v45.33,79.21
  Bottom 0.762: v45.33,68.54 39.24,62.45 33.14,62.45 28.57,57.87 IC11.36 | v45.33,79.21 42.29,82.26 37.71,82.26 36.19,80.73 PORTA.6
N$26
  Top 0.762: IC11.35 31.11,57.87 29.59,59.4 29.59,81.24 30.6,82.26 38.73,82.26 PORTA.8
N$27  (via drill 0.61)
  Top 0.762: v34.67,72.61 34.67,58.89 33.65,57.87 IC11.34
  Bottom 0.762: v34.67,72.61 37.21,75.15 40.76,75.15 42.79,77.18 42.79,80.23 41.27,80.23 PORTA.10
N$28
  Top 0.762: IC11.33 36.19,57.87 37.21,58.89 37.21,69.05 41.27,73.11 PORTA.9
N$29
  Top 0.762: R9.1 S3.1
  Bottom 0.762: 49.65,92.67 47.87,90.89 41.27,90.89 R9.1 | 49.65,92.67 51.43,94.45 S2.1 | S1.1 61.59,94.45 59.56,92.42 49.91,92.42 49.65,92.67
N$30
  Bottom 0.254: Q6.B 8.76,27.9 11.3,27.9 11.81,28.41 R19.2
N$31
  Bottom 0.254: Q3.B 8.76,45.68 11.3,45.68 11.81,46.19 R17.2
N$32
  Top 0.254: Q4.C Q2.C
  Bottom 0.254: SCHIENE1.1 2.15,55.33 6.22,55.33 8.25,57.37 Q4.C
N$33
  Bottom 0.406: 69.21,6.82 69.21,99.53
N$34
  Top 0.254: R18.2 5.71,58.89 Q4.B Q2.B 5.71,48.73 Q3.C
N$35
  Top 0.254: Q7.C Q5.C
  Bottom 0.254: SCHIENE2.1 2.15,37.55 6.22,37.55 8.25,39.59 Q7.C
N$36
  Top 0.406: 69.21,6.82 69.21,99.53
N$37
  Top 0.254: R20.2 5.71,41.11 Q7.B Q5.B 5.71,30.95 Q6.C
N$38
  Top 0.254: IC2.3 78.35,81.75 78.35,83.78 81.91,87.34 83.94,87.34 83.94,91.91 79.88,95.97 74.29,95.97 X1.3
N$40  (via drill 0.61)
  Top 0.254: PROG1.5 80.89,50.25 80.89,53.81 77.34,57.37 77.34,63.97 IC3.29 | v82.42,72.1 82.42,80.23 R25.2
  Bottom 0.254: v82.42,72.1 82.42,48.73 PROG1.5
N$41  (via drill 0.61)
  Top 0.254: v75.31,65.49 75.31,70.07 73.78,71.59 73.78,72.61 IC3.16
  Bottom 0.254: v75.31,65.49 75.31,55.33 77.85,55.33 PROG1.9
N$42  (via drill 0.61)
  Top 0.254: v70.73,71.59 70.73,71.08 72.26,71.08 IC3.17
  Bottom 0.254: v70.73,71.59 80.89,61.43 80.89,51.27 PROG1.7
N$43  (via drill 0.61)
  Top 0.254: v75.81,71.08 74.8,72.1 74.8,72.61 IC3.15
  Bottom 0.254: v75.81,71.08 76.83,70.07 78.35,70.07 81.4,73.11 82.93,73.11 83.43,72.61 83.43,43.65 PROG1.1
N$44
  Top 0.254: 75.81,92.93 74.29,92.93 73.78,92.42 73.78,91.4 74.29,90.89 74.29,88.35 75.81,88.35 R30.1 | 75.81,92.93 75.81,92.42 D1.3 75.81,92.93 | 75.81,92.93 75.81,94.45 X1.5
N$45  (via drill 0.61)
  Top 0.254: C5.1 73.27,89.88 73.27,88.35 IC1.3 | v77.85,88.35 77.85,89.37 77.34,89.88 D1.2 | v81.4,91.91 81.4,90.39 D2.2
  Bottom 0.254: IC1.3 73.27,88.35 v77.85,88.35 v81.4,91.91
N$46
  Top 0.254: D2.3 79.88,92.42 77.34,92.42 77.34,93.94 76.83,94.45 X1.7
N$52  (via drill 0.61)
  Top 0.254: v75.81,83.78 75.81,81.75 IC2.5 | v72.26,92.93 72.77,93.43 72.77,94.45 X1.1
  Bottom 0.254: v75.81,83.78 79.37,87.34 79.88,87.34 82.42,89.88 82.42,92.93 v72.26,92.93
N$53
  Top 0.254: IC3.13 76.32,73.11 76.32,74.64 76.83,75.15 IC2.13
N$54  (via drill 0.61)
  Top 0.254: v77.34,71.08 77.34,72.61 IC3.12 | v76.83,77.69 75.81,76.67 75.81,75.65 IC2.12
  Bottom 0.254: v77.34,71.08 77.34,77.69 v76.83,77.69
N$55
  Top 0.254: 82.42,85.31 82.42,86.32 R29.2 | 82.42,85.31 81.4,84.29 81.4,79.72 80.39,78.7 | 80.39,78.7 78.35,76.67 78.35,75.65 IC2.14 | 82.42,85.31 R28.1 | 80.39,78.7 76.32,78.7 74.8,77.18 74.8,76.16 74.29,75.65 IC2.11
N$56  (via drill 0.61)
  Top 0.254: v72.77,73.62 72.77,74.13 74.8,74.13 75.81,73.11 IC3.14 | v74.29,84.29 75.81,85.81 75.81,86.32 R30.2
  Bottom 0.254: v72.77,73.62 72.77,84.29 v74.29,84.29
N$122
  Top 0.254: R15.1 R14.1 IC11.40
  Bottom 0.254: R14.1 19.93,63.97 33.65,77.69 PORTA.3
N$135  (via drill 0.61)
  Top 0.254: 26.03,14.69 31.11,19.77 IC11.6 | v17.9,6.57 26.03,14.69 | 26.03,14.69 R2.2
  Bottom 0.254: PROG.1 6.73,6.57 v17.9,6.57
N$136
  Top 0.254: R3.2 33.65,15.71 IC11.7
  Bottom 0.254: PROG.9 6.73,16.73 30.09,16.73 R3.2
N$147
  Top 0.254: LCD.3 56.51,16.73 53.97,16.73 51.94,18.76 51.94,41.62 51.43,42.13 IC11.14
  Bottom 0.254: LCD.3 54.99,16.73 53.97,16.73 53.46,17.23 17.39,17.23 17.39,20.79 18.41,21.81 R11.1
N$149
  Bottom 0.254: R7.1 20.95,78.19 17.39,78.19 T3.1
N$150
  Top 0.254: R12.1 17.39,22.31 17.39,41.11 18.41,42.13 IC11.1 18.41,42.63 19.43,43.65 19.43,78.7 20.95,80.23 R5.1
N$152
  Top 0.254: IC11.12 46.35,38.57 45.33,37.55 Q1.2 45.33,37.05 45.33,33.49 46.35,32.47 C8.2
N$153
  Top 0.254: C9.2 49.91,32.47 49.91,37.05 Q1.1 49.91,37.55 49.91,41.11 48.89,42.13 IC11.13
N$156  (via drill 0.61)
  Top 0.254: IC11.9 R13.1 37.71,37.55 37.71,12.66 v37.21,12.15
  Bottom 0.254: PROG.5 7.23,12.15 v37.21,12.15
N$157
  Top 0.254: PROG.4 1.65,9.61 1.65,21.81 10.79,21.81 R11.2
N$158
  Bottom 0.254: PROG.6 1.65,10.63 1.65,15.71 3.17,17.23 8.76,17.23 10.79,19.27 R10.2
N$159
  Bottom 0.254: PROG.3 R12.2
N$160
  Top 0.254: IC11.24 59.05,57.87 64.13,62.95 PORTC.2
  Bottom 0.254: S3.2 43.81,94.96 45.33,96.48 64.64,96.48 65.65,95.47 65.65,78.19 64.13,78.19 PORTC.2
N$161
  Top 0.254: LCD.1 52.45,19.77 52.45,40.6 53.97,42.13 IC11.15
  Bottom 0.254: LCD.1 19.43,18.25 18.41,19.27 R10.1
N$164
  Top 0.254: IC11.3 23.49,42.63 21.97,44.16 21.97,69.05 20.95,70.07 R7.2
N$166
  Top 0.254: IC11.2 20.95,42.63 19.93,43.65 19.93,71.59 23.49,75.15 R6.1
N$167
  Top 0.254: R5.2 20.95,88.35 17.39,88.35 T1.1
N$168
  Top 0.254: R6.2 23.49,83.27 17.39,83.27 T2.1
N$170
  Top 0.254: IC11.8 36.19,11.65 36.7,11.14 38.73,11.14 R4.2
  Bottom 0.254: PROG.7 37.71,13.17 38.73,14.19 R4.2
N$172
  Bottom 0.762: WEICHE1.1 2.15,88.35 7.23,88.35 R21.2 9.27,90.39 14.35,90.39 14.35,88.35 T1.2
N$173
  Bottom 0.762: 7.49,85.05 7.23,85.31 2.15,85.31 WEICHE2.1 | 7.49,85.05 R22.2 | T2.2 14.35,83.27 14.35,85.31 7.74,85.31 7.49,85.05
N$174
  Bottom 0.762: 7.49,79.97 4.69,82.77 2.15,82.77 WEICHE3.1 | 7.49,79.97 R23.2 | T3.2 14.35,78.19 14.35,80.23 7.74,80.23 7.49,79.97
VCC
  Top 0.762: R14.2 C3.1 IC12.1 | R13.2 41.27,33.49 IC11.10
  Bottom 0.762: 47.87,82.26 47.87,70.57 L1.1 | 47.87,82.26 54.99,82.26 56.51,80.73 PORTC.7 | R14.2 26.03,66 36.19,76.16 37.21,76.16 38.73,77.69 PORTA.7 | C3.1 29.59,91.91 32.13,94.45 C4.+ 35.68,94.45 36.95,93.18 | 36.95,93.18 47.87,82.26 | PROG.2 4.69,4.03 18.92,4.03 25.52,10.63 53.97,10.63 60.32,16.98 | 60.32,16.98 LCD.7 | R13.2 47.37,22.31 64.64,22.31 64.89,22.06 | 64.89,22.06 65.65,21.3 65.65,16.73 60.57,16.73 60.32,16.98 | 36.95,93.18 41.27,97.5 66.67,97.5 68.19,95.97 68.19,22.31 65.15,22.31 64.89,22.06
VCC1
  Top 0.762: Q7.E R20.1 | Q4.E R18.1 6.73,61.43 6.73,72.61 6.98,72.86 | 6.98,72.86 6.73,73.11 6.73,75.15 6.98,75.4 | 6.98,72.86 R24.1 | 6.98,75.4 R23.1 | 6.98,80.48 6.73,80.23 6.73,75.65 6.98,75.4 | 6.98,80.48 R22.1 | 6.98,85.56 6.73,85.31 6.73,80.73 6.98,80.48 | 6.98,85.56 R21.1 | C2.1 IC12.3 | 2.15,94.45 2.15,90.89 WEICHE-ANODE.1 6.98,85.56 | 2.15,94.45 C1.+ | 2.15,94.45 12V.1
  Bottom 0.762: R20.1 9.77,44.67 7.23,44.67 5.71,46.19 5.71,50.25 11.3,50.25 12.31,51.27 12.31,57.37 10.79,57.37 Q4.E | C2.1 13.33,94.45 C1.+
VCC2  (via drill 0.61)
  Top 0.254: C10.1 73.27,83.78 73.27,85.31 IC1.1 73.78,86.32 73.78,87.34 76.83,87.34 77.34,86.83 77.34,82.26 76.83,81.75 IC2.4 | R28.2 82.42,83.27 82.42,82.26 R25.1 82.93,82.26 83.94,81.24 83.94,71.59 81.91,69.56 | 82.42,68.03 81.4,68.03 IC3.4 | 82.42,68.03 82.42,69.05 81.91,69.56 | 81.91,69.56 81.4,69.56 IC3.6 80.89,69.56 v79.37,69.56 | IC3.18 72.26,70.57 70.73,70.57 70.73,49.75 PROG1.2 76.83,42.13 79.37,42.13 82.42,45.17 82.42,68.03
  Bottom 0.254: v79.37,69.56 75.81,69.56 74.8,70.57 74.29,70.57 71.75,73.11 71.75,84.29 IC1.1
